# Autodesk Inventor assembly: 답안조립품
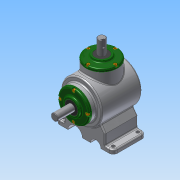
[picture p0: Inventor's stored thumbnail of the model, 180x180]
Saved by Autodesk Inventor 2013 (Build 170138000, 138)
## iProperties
Created: 2018-08
Part Number: 답안조립품
Document SubType Name: Assembly
Designer: user
Author: user
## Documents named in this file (14)
- C:\Users\user\Desktop\480808V1017\답안조립품.iam
- C:\Users\user\Desktop\480808V1017\본체.ipt
- C:\Users\user\Desktop\480808V1017\메인 축.ipt
- 메인 축.ipt
- C:\Users\user\Desktop\480808V1017\키 5x5.ipt
- C:\Users\user\Desktop\480808V1017\베어링 6203.ipt
- C:\Users\user\Desktop\480808V1017\메인 베벨기어.ipt
- C:\Users\user\Desktop\480808V1017\서브 축.ipt
- 서브 축.ipt
- C:\Users\user\Desktop\480808V1017\키 4x4.ipt
- C:\Users\user\Desktop\480808V1017\서브 베벨기어.ipt
- C:\Users\user\Desktop\480808V1017\커버.ipt
- C:\Users\user\Desktop\480808V1017\오일실 17 32 8.ipt
- C:\Users\user\Desktop\480808V1017\볼트 M4.ipt
